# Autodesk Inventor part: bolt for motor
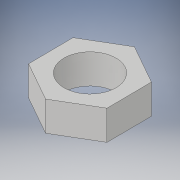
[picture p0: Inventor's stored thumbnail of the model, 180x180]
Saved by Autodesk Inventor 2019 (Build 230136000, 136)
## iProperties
Created: 2019-10
Part Number: bolt for motor
Material: Generic
Document SubType Name: Modeling
Designer: Asus
Density: 1 g/cm^3
Appearance: Default
Author: Asus
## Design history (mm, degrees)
sketch "Sketch1"
  geometry: 1 further point
sketch "Sketch2"
  geometry: L1 (10.441, 6.163)-(10.558, -5.961); L2 (10.558, -5.961)-(0.117, -12.124); L3 (0.117, -12.124)-(-10.441, -6.163); L4 (-10.441, -6.163)-(-10.558, 5.961); L5 (-10.558, 5.961)-(-0.117, 12.124); L6 (-0.117, 12.124)-(10.441, 6.163); 2 further points
  constraints: 12 end point, 1 coincident, 13 other
  dimensions: "d0" = 21 distance between parallel lines of L4 L1
extrude "Extrusion1" new body sketch "Sketch2" distance "d1" = 8; taper "d2" = 0 deg
sketch "Sketch3"
  geometry: C1 r 7 at (0, 0); 1 further point
  constraints: 1 centre point, 1 coincident
  dimensions: "d3" = 14 diameter of C1
extrude "Extrusion2" cut sketch "Sketch3" distance "d4" = 18; taper "d5" = 0 deg
body "Solid1"
